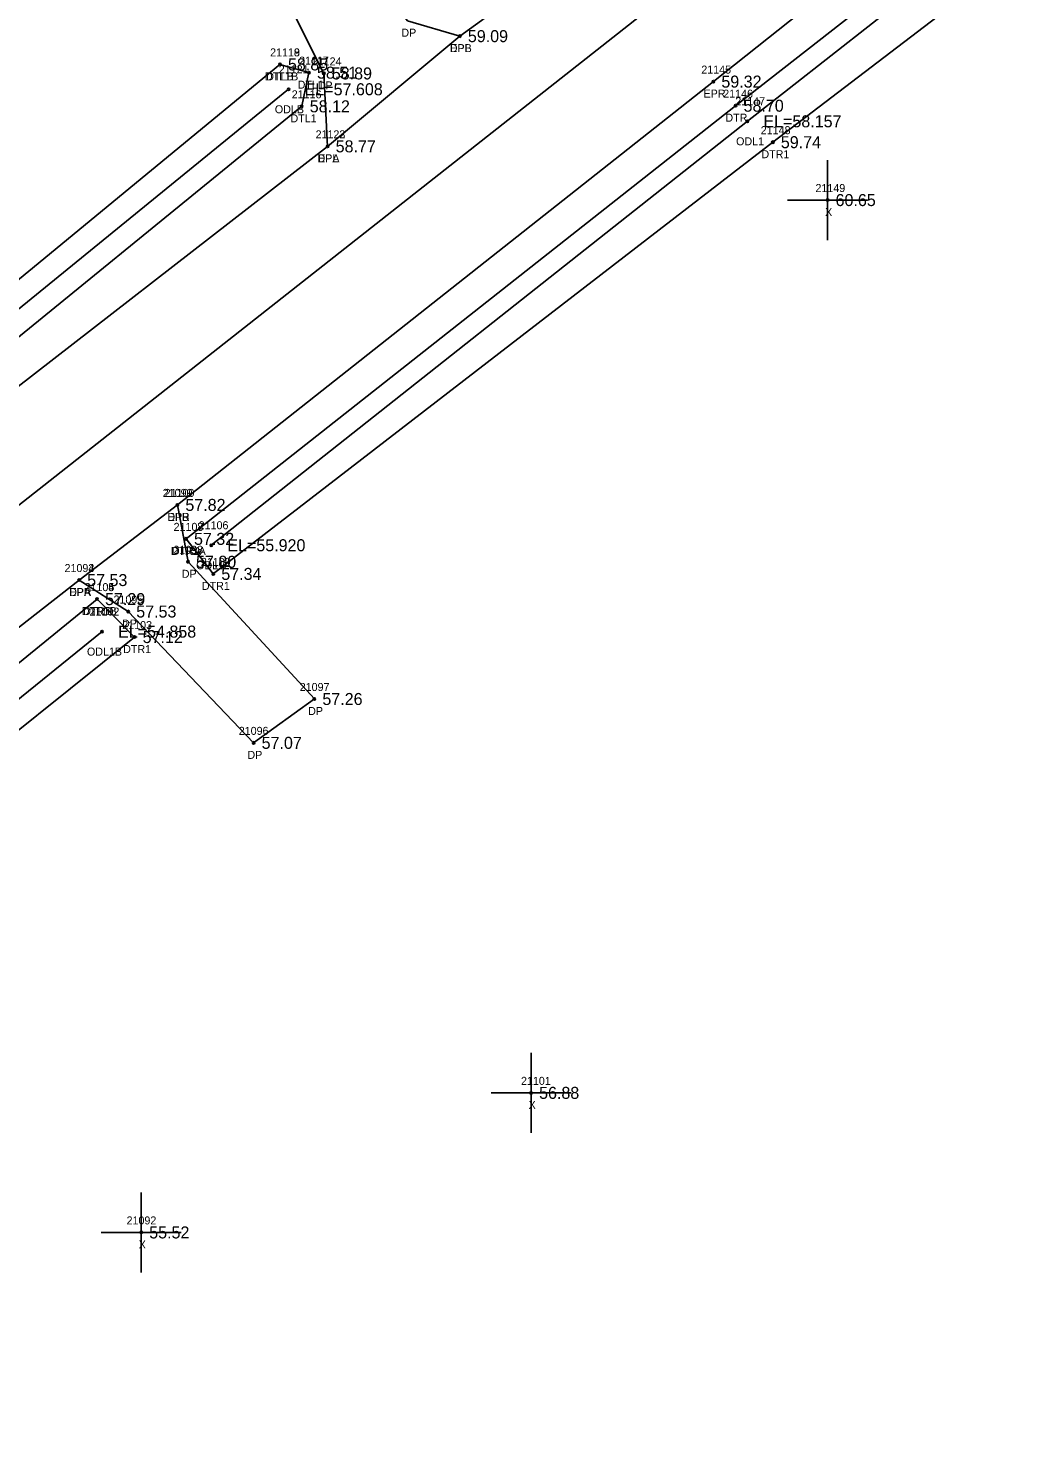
# Model space of a CAD drawing. Extents: x 2420351 to 2422725, y 845330 to 846558.
# Drawn here: x 2422363.4 to 2422489.2, y 846134.8 to 846312.6 of the extents above; entities that cross this region are included whole.
import ezdxf

# ---------------------------------------------------------------- set-up
doc = ezdxf.new("R2010")
doc.units = 0
for name, color, linetype in [('RD_DTM_BkLn1', 7, 'Continuous'), ('RD_EX_Driveway', 7, 'Continuous'), ('RD_EX_Driveway_txCode', 7, 'Continuous'), ('RD_EX_H2O', 7, 'Continuous'), ('RD_EX_H2O_txCode', 7, 'Continuous'), ('RD_EX_Misc', 7, 'Continuous'), ('RD_EX_Misc_txCode', 7, 'Continuous'), ('RD_EX_Road', 7, 'Continuous'), ('RD_EX_Road_txCode', 7, 'Continuous'), ('RD_EX_TX_Driveway_ELEV', 7, 'Continuous'), ('RD_EX_TX_H2O_ELEV', 7, 'Continuous'), ('RD_EX_TX_Misc_ELEV', 7, 'Continuous'), ('RD_EX_TX_Road_ELEV', 7, 'Continuous'), ('RD_SMD_Locator', 7, 'Continuous')]:
    doc.layers.add(name, color=color, linetype=linetype)

msp = doc.modelspace()

# ---------------------------------------------------------------- linework, layer by layer
at = {"layer": 'RD_DTM_BkLn1'}
msp.add_lwpolyline([(2421809.69, 845832.82), (2421858.88, 845863.61), (2421946.63, 845925.83), (2421988.11, 845958.04), (2422060.85, 846015.47), (2422145.87, 846082.37), (2422217.73, 846139.26), (2422291.07, 846197.06), (2422441.76, 846315.63), (2422509.48, 846369.12), (2422585.38, 846428.46), (2422650.19, 846479.15)], dxfattribs=at)
at = {"layer": 'RD_EX_Driveway'}
for points in [[(2422400.82, 846297.88), (2422400.34, 846306.99), (2422393.87, 846319.89), (2422401.53, 846325.2), (2422410.81, 846313.58), (2422417.34, 846311.65)], [(2422369.77, 846243.69), (2422375.9, 846239.76), (2422391.57, 846223.35), (2422399.16, 846228.83), (2422383.37, 846245.97), (2422382.04, 846253.08)]]:
    msp.add_lwpolyline(points, dxfattribs=at)
at = {"layer": 'RD_EX_H2O'}
for points in [[(2422383.12, 846248.84), (2422451.79, 846302.96), (2422519.84, 846356.14), (2422594.22, 846416.85), (2422660.96, 846466.59)], [(2422386.28, 846248.04), (2422453.27, 846301.01), (2422520.96, 846354.14), (2422596.31, 846414.61), (2422662.29, 846464.81)], [(2422383.12, 846248.84), (2422386.53, 846244.46), (2422456.45, 846298.4), (2422524.56, 846350.4), (2422601.29, 846410.12), (2422664.82, 846461.69)], [(2422286.3, 846221.38), (2422347.38, 846269.09), (2422394.86, 846308.12)], [(2422286.3, 846221.38), (2422288.87, 846218.14), (2422351.37, 846265.24), (2422397.58, 846302.88), (2422398.48, 846307.09), (2422394.86, 846308.12)], [(2422290.59, 846222.05), (2422349.1, 846266.91), (2422395.94, 846305.01)], [(2422251.76, 846136.81), (2422248.26, 846141.95), (2422300.54, 846183.09), (2422372, 846241.31)], [(2422251.76, 846136.81), (2422304.02, 846178.35), (2422376.7, 846236.57), (2422372, 846241.31)], [(2422252.08, 846140.11), (2422302.68, 846180.63), (2422372.63, 846237.25)]]:
    msp.add_lwpolyline(points, dxfattribs=at)
at = {"layer": 'RD_EX_Misc'}
for p, q in [((2422463.29, 846286.17), (2422463.29, 846296.17)), ((2422458.29, 846291.17), (2422468.29, 846291.17)), ((2422426.24, 846174.62), (2422426.24, 846184.62)), ((2422421.24, 846179.62), (2422431.24, 846179.62)), ((2422377.52, 846157.18), (2422377.52, 846167.18)), ((2422372.52, 846162.18), (2422382.52, 846162.18))]:
    msp.add_line(p, q, dxfattribs=at)
at = {"layer": 'RD_EX_Road'}
for points in [[(2421810.77, 845819.82), (2421809.69, 845832.82), (2421803.88, 845842.86), (2421852.96, 845873.69), (2421939.48, 845935.12), (2421980.78, 845967.01), (2422140.12, 846092.81), (2422210.03, 846148.43), (2422282.88, 846205.21), (2422291.79, 846212.09), (2422354.49, 846261.98), (2422400.82, 846297.88), (2422417.34, 846311.65), (2422435.4, 846324.77), (2422462.49, 846346.77), (2422472.85, 846354.85), (2422502.3, 846378.16), (2422578.05, 846437.54), (2422605.64, 846459.09), (2422626.64, 846476.17), (2422642.61, 846488.86)], [(2421810.77, 845819.82), (2421865.31, 845853.52), (2421953.26, 845916.07), (2421995.06, 845948.03), (2422068.36, 846005.98), (2422153.46, 846073.36), (2422229.55, 846134.03), (2422245.4, 846145.63), (2422297.08, 846186.88), (2422369.77, 846243.69), (2422382.04, 846253.08), (2422449.02, 846305.97), (2422517.14, 846360.1), (2422592.58, 846419.1), (2422657.51, 846470.1)]]:
    msp.add_lwpolyline(points, dxfattribs=at)
at = {"layer": 'RD_SMD_Locator'}
for centre in [(2422417.34, 846311.65), (2422417.34, 846311.65), (2422394.86, 846308.12), (2422394.86, 846308.12), (2422398.48, 846307.09), (2422400.34, 846306.99), (2422449.02, 846305.97), (2422395.94, 846305.01), (2422397.58, 846302.88), (2422451.79, 846302.96), (2422453.27, 846301.01), (2422400.82, 846297.88), (2422400.82, 846297.88), (2422456.45, 846298.4), (2422463.29, 846291.17), (2422382.04, 846253.08), (2422382.04, 846253.08), (2422383.12, 846248.84), (2422383.12, 846248.84), (2422386.28, 846248.04), (2422383.37, 846245.97), (2422369.77, 846243.69), (2422369.77, 846243.69), (2422386.53, 846244.46), (2422372, 846241.31), (2422372, 846241.31), (2422375.9, 846239.76), (2422372.63, 846237.25), (2422376.7, 846236.57), (2422399.16, 846228.83), (2422391.57, 846223.35), (2422426.24, 846179.62), (2422377.52, 846162.18)]:
    msp.add_circle(centre, 0.15, dxfattribs=at)

# ---------------------------------------------------------------- texts
at = {"layer": 'RD_EX_Driveway_txCode'}
for s, p in [('DP', (2422410.03, 846311.58)), ('DPB', (2422416.08, 846309.65)), ('21124', (2422398.83, 846307.99)), ('DP', (2422399.57, 846304.99)), ('21123', (2422399.31, 846298.88)), ('DPA', (2422399.55, 846295.88)), ('21099', (2422380.21, 846254.08)), ('DPB', (2422380.79, 846251.08)), ('21098', (2422381.54, 846246.97)), ('21094', (2422367.94, 846244.69)), ('DP', (2422382.59, 846243.97)), ('DPA', (2422368.51, 846241.69)), ('21095', (2422374.06, 846240.76)), ('DP', (2422375.12, 846237.76)), ('21097', (2422397.33, 846229.83)), ('DP', (2422398.38, 846226.83)), ('21096', (2422389.71, 846224.35)), ('DP', (2422390.79, 846221.35))]:
    msp.add_text(s, height=1, dxfattribs=at).set_placement(p)
at = {"layer": 'RD_EX_H2O_txCode'}
for s, p in [('21118', (2422393.63, 846309.12)), ('21119', (2422393.63, 846309.12)), ('21121', (2422394.71, 846307.01)), ('21117', (2422397.25, 846308.09)), ('DTL1B', (2422392.98, 846306.12)), ('DTLB', (2422393.14, 846306.12)), ('DTL1', (2422397.07, 846305.09)), ('21116', (2422396.33, 846303.88)), ('21146', (2422450.25, 846303.96)), ('ODLB', (2422394.22, 846302.01)), ('21147', (2422451.76, 846303.01)), ('DTL1', (2422396.17, 846300.88)), ('DTR', (2422450.52, 846300.96)), ('ODL1', (2422451.86, 846298.01)), ('21148', (2422454.94, 846299.4)), ('DTR1', (2422455.02, 846296.4)), ('21107', (2422381.57, 846249.84)), ('21108', (2422381.57, 846249.84)), ('21106', (2422384.7, 846250.04)), ('DTR1A', (2422381.2, 846246.84)), ('DTRA', (2422381.36, 846246.84)), ('ODL1A', (2422384.38, 846245.04)), ('21109', (2422384.98, 846245.46)), ('21104', (2422370.44, 846242.31)), ('21105', (2422370.44, 846242.31)), ('DTR1', (2422385.1, 846242.46)), ('DTR1B', (2422370.09, 846239.31)), ('DTRB', (2422370.26, 846239.31)), ('21102', (2422371.07, 846239.25)), ('21103', (2422375.15, 846237.57)), ('ODL1B', (2422370.74, 846234.25)), ('DTR1', (2422375.26, 846234.57))]:
    msp.add_text(s, height=1, dxfattribs=at).set_placement(p)
at = {"layer": 'RD_EX_Misc_txCode'}
for s, p in [('21149', (2422461.78, 846292.17)), ('X', (2422462.98, 846289.17)), ('21101', (2422424.98, 846180.62)), ('X', (2422425.93, 846177.62)), ('21092', (2422375.69, 846163.18)), ('X', (2422377.21, 846160.18))]:
    msp.add_text(s, height=1, dxfattribs=at).set_placement(p)
at = {"layer": 'RD_EX_Road_txCode'}
for s, p in [('EPL', (2422416.13, 846309.65)), ('21145', (2422447.51, 846306.97)), ('EPR', (2422447.79, 846303.97)), ('21122', (2422399.31, 846298.88)), ('EPL', (2422399.62, 846295.88)), ('21100', (2422380.45, 846254.08)), ('EPR', (2422380.82, 846251.08)), ('21093', (2422367.94, 846244.69)), ('EPR', (2422368.55, 846241.69))]:
    msp.add_text(s, height=1, dxfattribs=at).set_placement(p)
at = {"layer": 'RD_EX_TX_Driveway_ELEV'}
for s, p in [('59.09', (2422418.34, 846310.9)), ('58.89', (2422401.34, 846306.24)), ('58.77', (2422401.82, 846297.13)), ('57.82', (2422383.04, 846252.33)), ('57.80', (2422384.37, 846245.22)), ('57.53', (2422370.77, 846242.94)), ('57.53', (2422376.9, 846239.01)), ('57.26', (2422400.16, 846228.08)), ('57.07', (2422392.57, 846222.6))]:
    msp.add_text(s, height=1.5, dxfattribs=at).set_placement(p)
at = {"layer": 'RD_EX_TX_H2O_ELEV'}
for s, p in [('58.85', (2422395.86, 846307.37)), ('58.85', (2422395.86, 846307.37)), ('58.51', (2422399.48, 846306.34)), ('EL=57.608', (2422397.94, 846304.26)), ('58.12', (2422398.58, 846302.13)), ('58.70', (2422452.79, 846302.21)), ('EL=58.157', (2422455.27, 846300.26)), ('59.74', (2422457.45, 846297.65)), ('57.32', (2422384.12, 846248.09)), ('57.32', (2422384.12, 846248.09)), ('EL=55.920', (2422388.28, 846247.29)), ('57.34', (2422387.53, 846243.71)), ('57.29', (2422373, 846240.56)), ('57.29', (2422373, 846240.56)), ('EL=54.858', (2422374.63, 846236.5)), ('57.12', (2422377.7, 846235.82))]:
    msp.add_text(s, height=1.5, dxfattribs=at).set_placement(p)
at = {"layer": 'RD_EX_TX_Misc_ELEV'}
for s, p in [('60.65', (2422464.29, 846290.42)), ('56.88', (2422427.24, 846178.87)), ('55.52', (2422378.52, 846161.43))]:
    msp.add_text(s, height=1.5, dxfattribs=at).set_placement(p)
at = {"layer": 'RD_EX_TX_Road_ELEV'}
for s, p in [('59.09', (2422418.34, 846310.9)), ('59.32', (2422450.02, 846305.22)), ('58.77', (2422401.82, 846297.13)), ('57.82', (2422383.04, 846252.33)), ('57.53', (2422370.77, 846242.94))]:
    msp.add_text(s, height=1.5, dxfattribs=at).set_placement(p)

doc.saveas('drawing.dxf')
